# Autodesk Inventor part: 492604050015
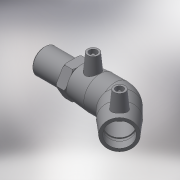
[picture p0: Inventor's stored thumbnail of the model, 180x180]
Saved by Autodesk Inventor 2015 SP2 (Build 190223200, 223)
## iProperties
Created: 2017-06
Part Number: 492604050015
Material: Generic
Description: PLASSON 45° ELBOW TRANSITION MALE 50-1.1/2"
Document SubType Name: Modeling
Designer: KIM
Mass: 314.479 g
Surface Area: 629.27 cm^2
Volume: 314.479 cm^3
Density: 1 g/cm^3
Appearance: Default
Author: KIM
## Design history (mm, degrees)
derived "492604.ipt"
feature "Solid1::492604.ipt"
tag "TaggingFeature1"
body "Solid1"
other parameters: "d2" = 67, "d4" = 32.5, "d5" = 60.3, "d8" = 168 deg, "d10" = 19.6, "d11" = 6.53333, "d29" = 51, "d30" = 15, "d31" = 45.5, "d34" = 5 deg, "d41" = 4, "d42" = 14, "d43" = 0, "d50" = 32.5, "d51" = 19.6, "d52" = 50.47, "d54" = 135 deg, "d86" = 30.15, "d87" = 135 deg, "d90" = 49, "d91" = 0, "d92" = 49, "d93" = 0, "d101" = 3, "d102" = 0, "d107" = 0.1, "d108" = 38, "d109" = 47.803, "d110" = 36, "d111" = 9, "d112" = 67, "d113" = 33.4621, "d114" = 32.4, "d116" = 2.01, "d122" = 0, "d123" = 2.39015, "L_" = 166, "L_1" = 49, "D_" = 38, "A_" = 51, "d_2" = 12, "L_2" = 36, "R_" = 47.803, "D_1" = 67
